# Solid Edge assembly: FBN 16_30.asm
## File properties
Title: Zylinder
Author: bmolnar
Template: iso assembly.asm
Last saved by: bmolnar
Revision: 20
Application: Solid Edge
Username: bmolnar
Dokumentum tartalom típus: 1
Document Number: FBN 16/30
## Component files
Kolbenstange.par
Profilrohr.par
Kit_1.par
Kit_2.par
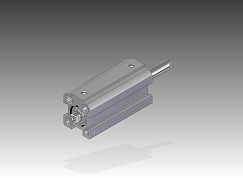
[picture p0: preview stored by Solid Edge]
